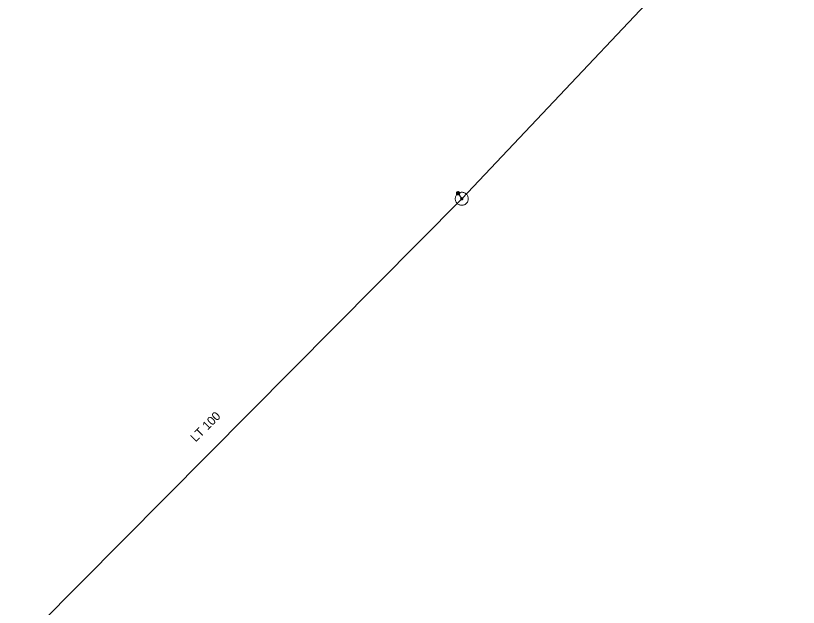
# Model space of a CAD drawing. Extents: x -687515 to -686506, y -974029 to -973461.
# Drawn here: x -687337.4 to -687277.6, y -973887.7 to -973842.5 of the extents above; entities that cross this region are included whole.
import ezdxf
from ezdxf.enums import TextEntityAlignment as Align

# ---------------------------------------------------------------- set-up
doc = ezdxf.new("R2010")
doc.units = 0
doc.header["$LTSCALE"] = 0.27
for name, color, linetype, lineweight in [('1', 7, 'Continuous', 13), ('14', 7, 'Continuous', 25), ('17', 7, 'Continuous', 25), ('47', 7, 'Continuous', 13), ('9', 7, 'Continuous', 13)]:
    doc.layers.add(name, color=color, linetype=linetype, lineweight=lineweight)

msp = doc.modelspace()

# ---------------------------------------------------------------- linework, layer by layer
at = {"layer": '14', "lineweight": 13}
msp.add_line((-687303.35, -973856.497), (-687303.629, -973856.079), dxfattribs=at)
at = {"layer": '17'}
msp.add_line((-687338.055, -973891.483), (-687303.35, -973856.497), dxfattribs=at)
msp.add_lwpolyline([(-687303.35, -973856.497), (-687281.82, -973833.708), (-687245.543, -973797.535), (-687243.233, -973793.923)], dxfattribs=at)
at = {"layer": '47'}
for points in [[(-687303.015, -973856.125), (-687303.056, -973856.092), (-687303.1, -973856.063), (-687303.146, -973856.04), (-687303.195, -973856.021), (-687303.246, -973856.007), (-687303.298, -973856), (-687303.35, -973855.997), (-687303.402, -973856), (-687303.453, -973856.008), (-687303.504, -973856.021), (-687303.553, -973856.04), (-687303.6, -973856.064), (-687303.643, -973856.092), (-687303.684, -973856.125), (-687303.721, -973856.162), (-687303.754, -973856.203), (-687303.783, -973856.247), (-687303.806, -973856.294), (-687303.825, -973856.342), (-687303.839, -973856.393), (-687303.846, -973856.445), (-687303.849, -973856.497), (-687303.847, -973856.55), (-687303.839, -973856.601), (-687303.825, -973856.651), (-687303.806, -973856.7), (-687303.782, -973856.747), (-687303.754, -973856.79), (-687303.721, -973856.831), (-687303.684, -973856.868), (-687303.643, -973856.901), (-687303.599, -973856.93), (-687303.553, -973856.954), (-687303.504, -973856.972), (-687303.453, -973856.986), (-687303.402, -973856.994), (-687303.349, -973856.997), (-687303.297, -973856.994), (-687303.245, -973856.986), (-687303.195, -973856.972), (-687303.146, -973856.953), (-687303.099, -973856.93), (-687303.056, -973856.901), (-687303.015, -973856.868), (-687302.978, -973856.831), (-687302.945, -973856.79), (-687302.916, -973856.746), (-687302.893, -973856.7), (-687302.874, -973856.651), (-687302.86, -973856.6), (-687302.852, -973856.549), (-687302.85, -973856.497), (-687302.852, -973856.445), (-687302.861, -973856.393), (-687302.874, -973856.342), (-687302.893, -973856.293), (-687302.917, -973856.247), (-687302.945, -973856.203), (-687302.978, -973856.162)], [(-687303.295, -973856.436), (-687303.301, -973856.43), (-687303.309, -973856.426), (-687303.316, -973856.422), (-687303.324, -973856.419), (-687303.332, -973856.416), (-687303.341, -973856.415), (-687303.35, -973856.414), (-687303.358, -973856.415), (-687303.366, -973856.417), (-687303.375, -973856.419), (-687303.383, -973856.422), (-687303.391, -973856.426), (-687303.398, -973856.43), (-687303.404, -973856.435), (-687303.41, -973856.442), (-687303.416, -973856.448), (-687303.42, -973856.456), (-687303.424, -973856.463), (-687303.427, -973856.471), (-687303.43, -973856.479), (-687303.431, -973856.488), (-687303.432, -973856.497), (-687303.431, -973856.505), (-687303.43, -973856.514), (-687303.427, -973856.522), (-687303.424, -973856.53), (-687303.42, -973856.538), (-687303.416, -973856.545), (-687303.411, -973856.551), (-687303.404, -973856.557), (-687303.398, -973856.563), (-687303.39, -973856.567), (-687303.383, -973856.571), (-687303.375, -973856.574), (-687303.367, -973856.577), (-687303.359, -973856.578), (-687303.349, -973856.579), (-687303.341, -973856.578), (-687303.332, -973856.577), (-687303.324, -973856.574), (-687303.316, -973856.571), (-687303.308, -973856.567), (-687303.301, -973856.563), (-687303.295, -973856.558), (-687303.289, -973856.551), (-687303.283, -973856.545), (-687303.279, -973856.537), (-687303.275, -973856.53), (-687303.272, -973856.522), (-687303.269, -973856.514), (-687303.268, -973856.506), (-687303.267, -973856.496), (-687303.268, -973856.488), (-687303.27, -973856.48), (-687303.272, -973856.471), (-687303.275, -973856.463), (-687303.279, -973856.455), (-687303.283, -973856.448), (-687303.288, -973856.442)]]:
    msp.add_lwpolyline(points, close=True, dxfattribs=at)
at = {"layer": '9'}
for points in [[(-687303.502, -973856.079), (-687303.504, -973856.066), (-687303.505, -973856.053), (-687303.509, -973856.04), (-687303.514, -973856.028), (-687303.519, -973856.016), (-687303.527, -973856.005), (-687303.534, -973855.995), (-687303.544, -973855.985), (-687303.554, -973855.977), (-687303.566, -973855.97), (-687303.578, -973855.964), (-687303.59, -973855.959), (-687303.603, -973855.956), (-687303.615, -973855.954), (-687303.629, -973855.953), (-687303.642, -973855.954), (-687303.654, -973855.956), (-687303.668, -973855.959), (-687303.679, -973855.964), (-687303.691, -973855.97), (-687303.703, -973855.977), (-687303.713, -973855.985), (-687303.723, -973855.995), (-687303.73, -973856.005), (-687303.738, -973856.016), (-687303.744, -973856.028), (-687303.749, -973856.04), (-687303.752, -973856.053), (-687303.754, -973856.066), (-687303.755, -973856.079), (-687303.754, -973856.092), (-687303.752, -973856.105), (-687303.749, -973856.118), (-687303.744, -973856.13), (-687303.738, -973856.142), (-687303.73, -973856.153), (-687303.723, -973856.163), (-687303.713, -973856.173), (-687303.703, -973856.181), (-687303.691, -973856.188), (-687303.679, -973856.194), (-687303.668, -973856.199), (-687303.654, -973856.202), (-687303.642, -973856.204), (-687303.629, -973856.205), (-687303.615, -973856.204), (-687303.603, -973856.202), (-687303.59, -973856.199), (-687303.578, -973856.194), (-687303.566, -973856.188), (-687303.554, -973856.181), (-687303.544, -973856.173), (-687303.534, -973856.163), (-687303.527, -973856.153), (-687303.519, -973856.142), (-687303.514, -973856.13), (-687303.509, -973856.118), (-687303.505, -973856.105), (-687303.504, -973856.092)], [(-687303.522, -973856.079), (-687303.522, -973856.068), (-687303.524, -973856.057), (-687303.527, -973856.046), (-687303.532, -973856.036), (-687303.537, -973856.026), (-687303.543, -973856.017), (-687303.549, -973856.008), (-687303.558, -973856), (-687303.566, -973855.993), (-687303.576, -973855.987), (-687303.586, -973855.982), (-687303.595, -973855.978), (-687303.607, -973855.975), (-687303.617, -973855.973), (-687303.629, -973855.973), (-687303.64, -973855.973), (-687303.651, -973855.975), (-687303.662, -973855.978), (-687303.671, -973855.982), (-687303.681, -973855.987), (-687303.691, -973855.993), (-687303.7, -973856), (-687303.708, -973856.008), (-687303.715, -973856.017), (-687303.72, -973856.026), (-687303.725, -973856.036), (-687303.73, -973856.046), (-687303.733, -973856.057), (-687303.735, -973856.068), (-687303.735, -973856.079), (-687303.735, -973856.09), (-687303.733, -973856.101), (-687303.73, -973856.112), (-687303.725, -973856.122), (-687303.72, -973856.132), (-687303.715, -973856.141), (-687303.708, -973856.15), (-687303.7, -973856.158), (-687303.691, -973856.165), (-687303.681, -973856.171), (-687303.671, -973856.176), (-687303.662, -973856.18), (-687303.651, -973856.183), (-687303.64, -973856.185), (-687303.629, -973856.185), (-687303.617, -973856.185), (-687303.607, -973856.183), (-687303.595, -973856.18), (-687303.586, -973856.176), (-687303.576, -973856.171), (-687303.566, -973856.165), (-687303.558, -973856.158), (-687303.549, -973856.15), (-687303.543, -973856.141), (-687303.537, -973856.132), (-687303.532, -973856.122), (-687303.527, -973856.112), (-687303.524, -973856.101), (-687303.522, -973856.09)], [(-687303.541, -973856.079), (-687303.543, -973856.07), (-687303.544, -973856.061), (-687303.546, -973856.052), (-687303.549, -973856.044), (-687303.554, -973856.036), (-687303.559, -973856.028), (-687303.565, -973856.021), (-687303.571, -973856.015), (-687303.578, -973856.009), (-687303.586, -973856.004), (-687303.593, -973856), (-687303.602, -973855.997), (-687303.61, -973855.994), (-687303.62, -973855.993), (-687303.629, -973855.992), (-687303.637, -973855.993), (-687303.647, -973855.994), (-687303.656, -973855.997), (-687303.664, -973856), (-687303.671, -973856.004), (-687303.679, -973856.009), (-687303.686, -973856.015), (-687303.693, -973856.021), (-687303.698, -973856.028), (-687303.703, -973856.036), (-687303.708, -973856.044), (-687303.711, -973856.052), (-687303.713, -973856.061), (-687303.715, -973856.07), (-687303.716, -973856.079), (-687303.715, -973856.088), (-687303.713, -973856.097), (-687303.711, -973856.106), (-687303.708, -973856.114), (-687303.703, -973856.122), (-687303.698, -973856.13), (-687303.693, -973856.137), (-687303.686, -973856.143), (-687303.679, -973856.149), (-687303.671, -973856.154), (-687303.664, -973856.158), (-687303.656, -973856.161), (-687303.647, -973856.164), (-687303.637, -973856.165), (-687303.629, -973856.166), (-687303.62, -973856.165), (-687303.61, -973856.164), (-687303.602, -973856.161), (-687303.593, -973856.158), (-687303.586, -973856.154), (-687303.578, -973856.149), (-687303.571, -973856.143), (-687303.565, -973856.137), (-687303.559, -973856.13), (-687303.554, -973856.122), (-687303.549, -973856.114), (-687303.546, -973856.106), (-687303.544, -973856.097), (-687303.543, -973856.088)], [(-687303.561, -973856.079), (-687303.561, -973856.072), (-687303.564, -973856.065), (-687303.565, -973856.058), (-687303.568, -973856.052), (-687303.571, -973856.046), (-687303.575, -973856.04), (-687303.578, -973856.034), (-687303.583, -973856.029), (-687303.59, -973856.025), (-687303.595, -973856.021), (-687303.602, -973856.018), (-687303.608, -973856.015), (-687303.615, -973856.014), (-687303.622, -973856.012), (-687303.629, -973856.012), (-687303.636, -973856.012), (-687303.642, -973856.014), (-687303.649, -973856.015), (-687303.656, -973856.018), (-687303.663, -973856.021), (-687303.668, -973856.025), (-687303.674, -973856.029), (-687303.679, -973856.034), (-687303.683, -973856.04), (-687303.686, -973856.046), (-687303.69, -973856.052), (-687303.693, -973856.058), (-687303.695, -973856.065), (-687303.696, -973856.072), (-687303.696, -973856.079), (-687303.696, -973856.086), (-687303.695, -973856.093), (-687303.693, -973856.1), (-687303.69, -973856.106), (-687303.686, -973856.113), (-687303.683, -973856.118), (-687303.679, -973856.124), (-687303.674, -973856.129), (-687303.668, -973856.133), (-687303.663, -973856.137), (-687303.656, -973856.14), (-687303.649, -973856.143), (-687303.642, -973856.145), (-687303.636, -973856.146), (-687303.629, -973856.146), (-687303.622, -973856.146), (-687303.615, -973856.145), (-687303.608, -973856.143), (-687303.602, -973856.14), (-687303.595, -973856.137), (-687303.59, -973856.133), (-687303.583, -973856.129), (-687303.578, -973856.124), (-687303.575, -973856.118), (-687303.571, -973856.113), (-687303.568, -973856.106), (-687303.565, -973856.1), (-687303.564, -973856.093), (-687303.561, -973856.086)], [(-687303.581, -973856.079), (-687303.581, -973856.074), (-687303.583, -973856.069), (-687303.583, -973856.064), (-687303.586, -973856.06), (-687303.588, -973856.055), (-687303.591, -973856.051), (-687303.593, -973856.048), (-687303.598, -973856.044), (-687303.6, -973856.041), (-687303.605, -973856.038), (-687303.61, -973856.036), (-687303.614, -973856.034), (-687303.619, -973856.033), (-687303.624, -973856.032), (-687303.629, -973856.032), (-687303.634, -973856.032), (-687303.639, -973856.033), (-687303.644, -973856.034), (-687303.647, -973856.036), (-687303.652, -973856.038), (-687303.657, -973856.041), (-687303.661, -973856.044), (-687303.664, -973856.048), (-687303.666, -973856.051), (-687303.669, -973856.055), (-687303.671, -973856.06), (-687303.674, -973856.064), (-687303.674, -973856.069), (-687303.676, -973856.074), (-687303.676, -973856.079), (-687303.676, -973856.084), (-687303.674, -973856.089), (-687303.674, -973856.094), (-687303.671, -973856.098), (-687303.669, -973856.103), (-687303.666, -973856.107), (-687303.664, -973856.111), (-687303.661, -973856.114), (-687303.657, -973856.117), (-687303.652, -973856.12), (-687303.647, -973856.122), (-687303.644, -973856.124), (-687303.639, -973856.125), (-687303.634, -973856.126), (-687303.629, -973856.126), (-687303.624, -973856.126), (-687303.619, -973856.125), (-687303.614, -973856.124), (-687303.61, -973856.122), (-687303.605, -973856.12), (-687303.6, -973856.117), (-687303.598, -973856.114), (-687303.593, -973856.111), (-687303.591, -973856.107), (-687303.588, -973856.103), (-687303.586, -973856.098), (-687303.583, -973856.094), (-687303.583, -973856.089), (-687303.581, -973856.084)], [(-687303.602, -973856.079), (-687303.602, -973856.076), (-687303.602, -973856.073), (-687303.603, -973856.071), (-687303.603, -973856.068), (-687303.605, -973856.065), (-687303.607, -973856.063), (-687303.608, -973856.061), (-687303.61, -973856.059), (-687303.613, -973856.057), (-687303.615, -973856.055), (-687303.617, -973856.054), (-687303.62, -973856.053), (-687303.622, -973856.052), (-687303.625, -973856.052), (-687303.629, -973856.052), (-687303.632, -973856.052), (-687303.635, -973856.052), (-687303.637, -973856.053), (-687303.64, -973856.054), (-687303.642, -973856.055), (-687303.644, -973856.057), (-687303.647, -973856.059), (-687303.649, -973856.061), (-687303.651, -973856.063), (-687303.652, -973856.065), (-687303.654, -973856.068), (-687303.654, -973856.071), (-687303.656, -973856.073), (-687303.656, -973856.076), (-687303.657, -973856.079), (-687303.656, -973856.082), (-687303.656, -973856.085), (-687303.654, -973856.088), (-687303.654, -973856.09), (-687303.652, -973856.093), (-687303.651, -973856.095), (-687303.649, -973856.098), (-687303.647, -973856.1), (-687303.644, -973856.101), (-687303.642, -973856.103), (-687303.64, -973856.104), (-687303.637, -973856.105), (-687303.635, -973856.106), (-687303.632, -973856.106), (-687303.629, -973856.107), (-687303.625, -973856.106), (-687303.622, -973856.106), (-687303.62, -973856.105), (-687303.617, -973856.104), (-687303.615, -973856.103), (-687303.613, -973856.101), (-687303.61, -973856.1), (-687303.608, -973856.098), (-687303.607, -973856.095), (-687303.605, -973856.093), (-687303.603, -973856.09), (-687303.603, -973856.088), (-687303.602, -973856.085), (-687303.602, -973856.082)], [(-687303.62, -973856.079), (-687303.62, -973856.078), (-687303.62, -973856.077), (-687303.622, -973856.077), (-687303.622, -973856.076), (-687303.622, -973856.075), (-687303.622, -973856.074), (-687303.622, -973856.074), (-687303.624, -973856.073), (-687303.624, -973856.073), (-687303.625, -973856.072), (-687303.625, -973856.072), (-687303.627, -973856.072), (-687303.627, -973856.071), (-687303.627, -973856.071), (-687303.629, -973856.071), (-687303.63, -973856.071), (-687303.63, -973856.071), (-687303.63, -973856.072), (-687303.632, -973856.072), (-687303.632, -973856.072), (-687303.634, -973856.073), (-687303.634, -973856.073), (-687303.635, -973856.074), (-687303.635, -973856.074), (-687303.636, -973856.075), (-687303.636, -973856.076), (-687303.637, -973856.077), (-687303.637, -973856.077), (-687303.637, -973856.078), (-687303.637, -973856.079), (-687303.637, -973856.08), (-687303.637, -973856.081), (-687303.637, -973856.081), (-687303.636, -973856.082), (-687303.636, -973856.083), (-687303.635, -973856.084), (-687303.635, -973856.084), (-687303.634, -973856.085), (-687303.634, -973856.085), (-687303.632, -973856.086), (-687303.632, -973856.086), (-687303.63, -973856.087), (-687303.63, -973856.087), (-687303.63, -973856.087), (-687303.629, -973856.087), (-687303.627, -973856.087), (-687303.627, -973856.087), (-687303.627, -973856.087), (-687303.625, -973856.086), (-687303.625, -973856.086), (-687303.624, -973856.085), (-687303.624, -973856.085), (-687303.622, -973856.084), (-687303.622, -973856.084), (-687303.622, -973856.083), (-687303.622, -973856.082), (-687303.622, -973856.081), (-687303.62, -973856.081), (-687303.62, -973856.08)]]:
    msp.add_lwpolyline(points, close=True, dxfattribs=at)

# ---------------------------------------------------------------- texts
at = {"layer": '1'}
msp.add_text('LT 100', height=0.6667, rotation=45, dxfattribs=at).set_placement((-687322.704, -973874.149), align=Align.CENTER)

doc.saveas('drawing.dxf')
